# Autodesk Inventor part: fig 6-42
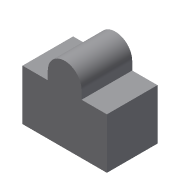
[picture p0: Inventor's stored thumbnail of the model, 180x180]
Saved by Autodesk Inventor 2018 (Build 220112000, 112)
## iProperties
Created: 2005-12
Part Number: fig 6-42
Document SubType Name: Modeling
Designer: CADCIM
Density: 1 g/cm^3
Material: Generic
Appearance: Default
Author: CADCIM
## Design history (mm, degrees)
sketch "Sketch1"
  geometry: L1 (10, 15)-(25, 15); L2 (25, 15)-(25, -15); L3 (25, -15)-(-25, -15); L4 (-25, -15)-(-25, 15); L5 (-25, 15)-(-10, 15); L6 (10, 15)-(10, 30); L7 (10, 30)-(-10, 30); L8 (-10, 30)-(-10, 15)
  constraints: 16 end point, 3 parallel, 3 perpendicular, 2 equal length, 1 collinear, 1 horizontal
  dimensions: "d0" = 50 distance of L2.end L3.end; "d2" = 30 distance of L1.end L2.end; "d3" = 15 distance of L1.start L1.end; "d11" = 15 distance of L7.end L5.end
extrude "Extrusion1" new body sketch "Sketch1" stored distance "d7" = 30; taper "d8" = 0 deg
fillet "Fillet5"
body "Solid1"
